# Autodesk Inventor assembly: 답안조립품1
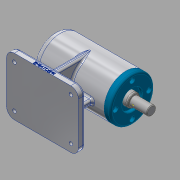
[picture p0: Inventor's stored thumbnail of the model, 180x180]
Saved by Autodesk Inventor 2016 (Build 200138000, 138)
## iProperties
Created: 2020-10
Part Number: 답안조립품1
Document SubType Name: Assembly
Designer: user
Author: user
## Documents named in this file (8)
- C:\Users\user\Desktop\701004V1004\답안조립품1.iam
- C:\Users\user\Desktop\701004V1004\1.본체.ipt
- C:\Users\user\Desktop\701004V1004\베어링 51202.ipt
- C:\Users\user\Desktop\701004V1004\어댑터슬리브.ipt
- C:\Users\user\Desktop\701004V1004\베어링 6004.ipt
- C:\Users\user\Desktop\701004V1004\축.ipt
- C:\Users\user\Desktop\701004V1004\커버.ipt
- C:\Users\user\Desktop\701004V1004\볼트 M4.ipt
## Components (1 placed, 1 different names)
1. 1.본체:1
